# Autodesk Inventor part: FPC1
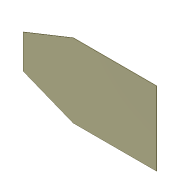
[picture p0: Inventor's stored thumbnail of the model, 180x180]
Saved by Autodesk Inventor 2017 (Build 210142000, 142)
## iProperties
Part Number: FPC1
Material: ポリプロピレン
Document SubType Name: Modeling
Designer: kyushu-hep
Density: 0.899 g/cm^3
Appearance: 滑らか - 灰色
Author: kyushu-hep
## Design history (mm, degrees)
sketch "スケッチ2"
  geometry: L1 (16.961, 8.668)-(16.961, -7.832); L2 (16.961, -7.832)-(-7.639, -17.632); L3 (-7.639, -17.632)-(-48.519, -17.632); L4 (-48.519, -17.632)-(-48.519, 18.468); L5 (-48.519, 18.468)-(-7.639, 18.468); L6 (-7.639, 18.468)-(16.961, 8.668); 1 further point
  constraints: 12 end point, 3 perpendicular, 1 equal length, 1 vertical
  dimensions: "d5" = 16.5 distance of L1.start L1.end; "d6" = 40.88 distance of L2.end L3.end; "d7" = 36.1 distance of L3.end L4.end; "d8" = 40.88 distance of L4.end L5.end; "d9" = 65.48 distance between parallel lines of L1 L4
extrude "押し出し1" new body sketch "スケッチ2" distance "d10" = 0.2; taper "d11" = 0 deg
node "ソリッド1"
